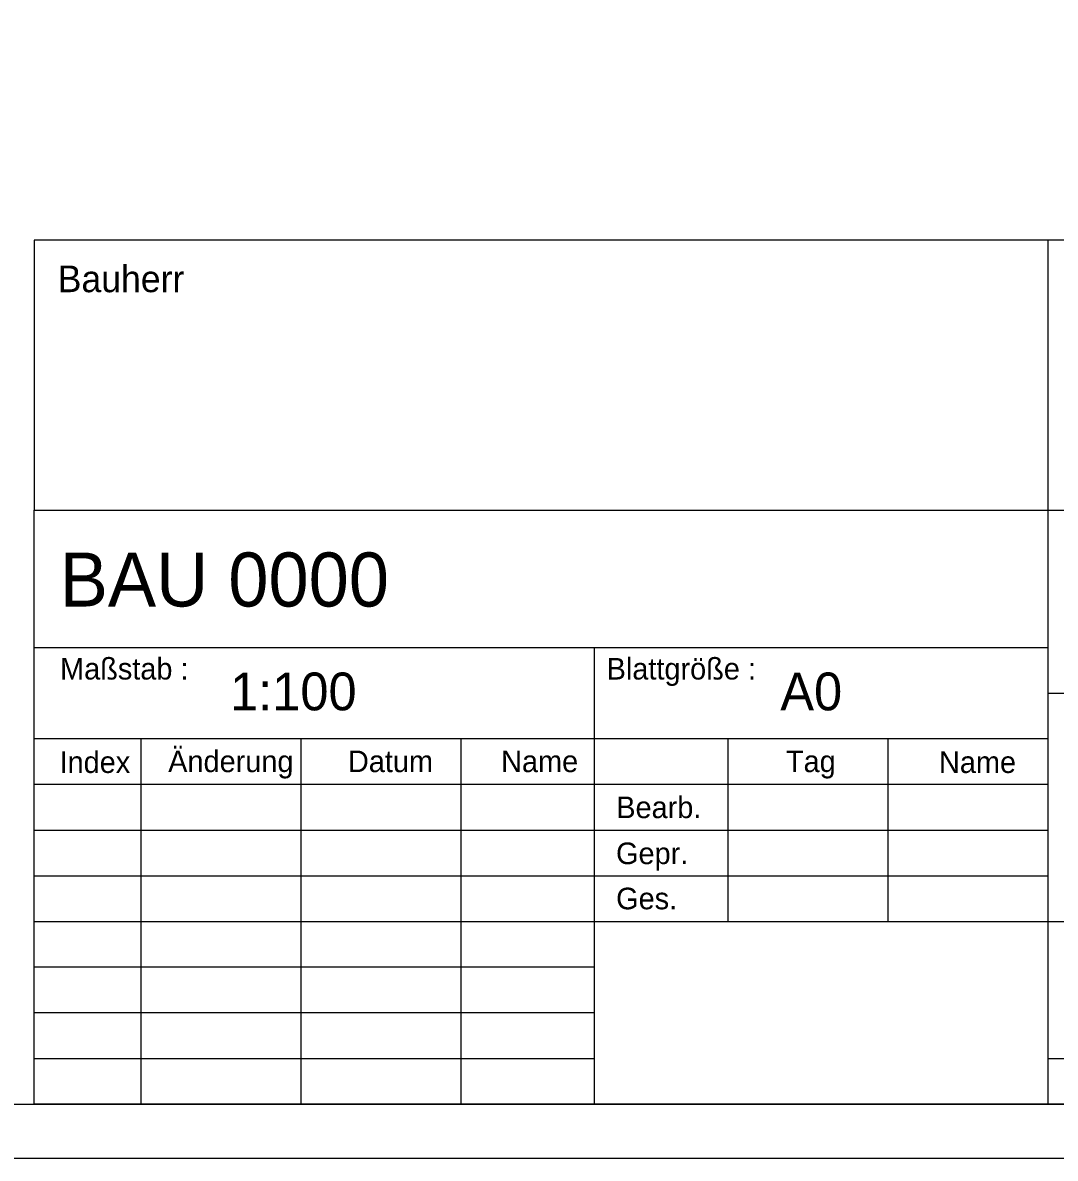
# Model space of a CAD drawing. Extents: x 0 to 119, y 0 to 84.
# Drawn here: x 100.51 to 110.07, y 0 to 10.51 of the extents above; entities that cross this region are included whole.
import ezdxf

# ---------------------------------------------------------------- set-up
doc = ezdxf.new("R2010")
doc.units = 0
doc.layers.add('90_Plankopf', color=7, linetype='Continuous')

msp = doc.modelspace()

# ---------------------------------------------------------------- linework, layer by layer
at = {"layer": '90_Plankopf'}
for p, q in [((118.4, 8.499), (100.612, 8.499)), ((100.612, 8.499), (100.612, 5.999)), ((110, 5.999), (110, 8.499)), ((100.612, 5.999), (118.4, 5.999)), ((100.612, 0.5), (100.612, 5.999)), ((100.612, 5.999), (118.4, 5.999)), ((110, 0.5), (110, 5.999)), ((100.612, 4.73), (110, 4.73)), ((105.8, 0.5), (105.8, 4.73)), ((110, 4.307), (118.4, 4.307)), ((100.612, 3.887), (110, 3.887)), ((101.6, 3.884), (101.6, 0.5)), ((103.083, 0.5), (103.083, 3.884)), ((104.565, 0.5), (104.565, 3.884)), ((107.035, 3.884), (107.035, 2.192)), ((108.518, 2.192), (108.518, 3.884)), ((100.612, 3.463), (110, 3.463)), ((100.612, 3.038), (110, 3.038)), ((100.612, 2.615), (110, 2.615)), ((100.612, 2.192), (110, 2.192)), ((100.612, 2.192), (110, 2.192)), ((105.8, 2.192), (110, 2.192)), ((110, 2.192), (118.4, 2.192)), ((105.8, 1.769), (100.612, 1.769)), ((105.8, 1.346), (100.612, 1.346)), ((100.612, 0.923), (105.8, 0.923)), ((110, 0.923), (118.4, 0.923)), ((118.4, 0.5), (100.612, 0.5)), ((100.612, 0.5), (105.8, 0.5)), ((101.78, 0.5), (118.4, 0.5)), ((101.78, 0.5), (118.4, 0.5))]:
    msp.add_line(p, q, dxfattribs=at)
for points in [[(0, 0), (118.9, 0), (118.9, 84.1), (0, 84.1)], [(2.5, 0.5), (118.4, 0.5), (118.4, 83.6), (2.5, 83.6)]]:
    msp.add_lwpolyline(points, close=True, dxfattribs=at)

# ---------------------------------------------------------------- texts
for s, height, p in [('Bauherr', 0.2464, (100.83, 8.018)), ('BAU 0000      ', 0.5, (100.849, 5.108)), ('Maßstab :', 0.2, (100.852, 4.432)), ('Blattgröße :', 0.19999, (105.912, 4.432)), ('1:100    ', 0.35, (102.426, 4.147)), ('A0       ', 0.35, (107.52, 4.147)), ('Änderung', 0.2, (101.853, 3.575)), ('Index', 0.2, (100.847, 3.567)), ('Datum', 0.2, (103.517, 3.575)), ('Name', 0.2, (104.935, 3.575)), ('Tag', 0.2, (107.572, 3.575)), ('Name', 0.2, (108.989, 3.567)), ('Bearb.', 0.2, (106.001, 3.149)), ('Gepr.', 0.2, (105.999, 2.723)), ('Ges.', 0.2, (106, 2.305))]:
    msp.add_text(s, height=height, dxfattribs=at).set_placement(p)

doc.saveas('drawing.dxf')
